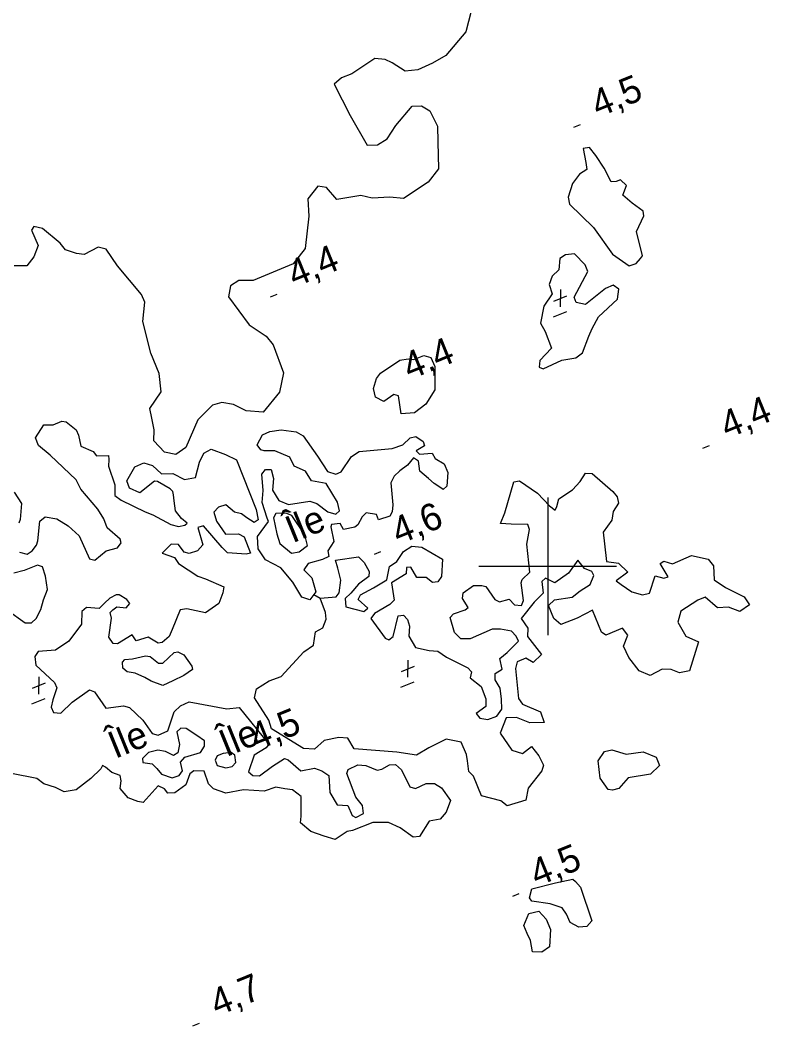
# Model space of a CAD drawing. Extents: x 362852 to 366875, y 5563573 to 5566479.
# Drawn here: x 364723.3 to 364831.6, y 5565333.2 to 5565479.3 of the extents above; entities that cross this region are included whole.
import ezdxf

# ---------------------------------------------------------------- set-up
doc = ezdxf.new("R2010")
doc.units = 0
for name, color, linetype in [('Niveau 3', 7, 'Continuous'), ('Niveau 4', 7, 'Continuous'), ('Niveau 61', 7, 'Continuous'), ('Niveau 8', 7, 'Continuous')]:
    doc.layers.add(name, color=color, linetype=linetype)

msp = doc.modelspace()

# ---------------------------------------------------------------- linework, layer by layer
at = {"layer": 'Niveau 3'}
for p, q in [((364803.8, 5565463.79), (364804.76, 5565464.18)), ((364801.85, 5565440.19), (364801.8, 5565437.67)), ((364759.71, 5565439.11), (364760.67, 5565439.5)), ((364800.91, 5565438.51), (364802.8, 5565439.3)), ((364800.83, 5565436.23), (364802.77, 5565437.02)), ((364822.55, 5565417.14), (364823.51, 5565417.53)), ((364774.81, 5565401.74), (364775.77, 5565402.13)), ((364779.68, 5565386.38), (364779.63, 5565383.87)), ((364778.74, 5565384.7), (364780.63, 5565385.49)), ((364725.13, 5565382.28), (364727.02, 5565383.07)), ((364726.07, 5565383.96), (364726.02, 5565381.44)), ((364778.66, 5565382.42), (364780.6, 5565383.21)), ((364725.05, 5565380), (364726.99, 5565380.79)), ((364794.91, 5565352.07), (364795.87, 5565352.46)), ((364748.44, 5565333.24), (364749.4, 5565333.63))]:
    msp.add_line(p, q, dxfattribs=at)
at = {"layer": 'Niveau 4'}
msp.add_line((364766.02, 5565395.89), (364766.96, 5565395.38), dxfattribs=at)
for points in [[(364789.2, 5565481.95), (364788.11, 5565477.64), (364785.18, 5565474.19), (364783.27, 5565473.09), (364781.14, 5565472.09), (364779.29, 5565471.89), (364777.42, 5565473.11), (364776.4, 5565473.62), (364774.86, 5565473.74), (364771.55, 5565471.5), (364770.04, 5565470.94), (364768.99, 5565470.01), (364771.3, 5565465.48), (364773.77, 5565461.14), (364775.25, 5565461.19), (364776.68, 5565462.09), (364777.93, 5565464.04), (364780.32, 5565466.83), (364781.67, 5565466.89), (364782.85, 5565466.13), (364784.01, 5565463.93), (364784.02, 5565461.63), (364784.15, 5565457.7), (364782.65, 5565455.77), (364779.07, 5565453.42), (364777.08, 5565453.6), (364774.51, 5565453.47), (364772.86, 5565453.85), (364769.37, 5565453.28), (364767.84, 5565455.02), (364766.59, 5565455.19), (364765.17, 5565453.36), (364765.27, 5565450.85), (364764.78, 5565446.16), (364763.02, 5565443.94), (364757.19, 5565441.48), (364755.13, 5565441.5), (364753.89, 5565440.74), (364753.62, 5565439.13), (364756.6, 5565435.07), (364759.09, 5565433.41), (364760.11, 5565432.15), (364761.6, 5565428.09), (364761.01, 5565425.3), (364758.66, 5565422.4), (364756.17, 5565422.55), (364754.35, 5565423.49), (364752.67, 5565423.79), (364751.28, 5565423.4), (364749.17, 5565421.29), (364747.41, 5565417.26), (364745.96, 5565416.23), (364744.34, 5565416.56), (364742.78, 5565418.22), (364742.81, 5565419.79), (364742.47, 5565421.52), (364742.21, 5565422.91), (364743.83, 5565425.32), (364743.53, 5565428), (364742.32, 5565430.93), (364741.16, 5565435.56), (364741.49, 5565438.37), (364740.98, 5565439.47), (364737.51, 5565443.65), (364735.83, 5565446.07), (364734.71, 5565446.36), (364732.67, 5565445.27), (364731.55, 5565445.43), (364729.96, 5565445.96), (364729.18, 5565446.94), (364726.62, 5565449.07), (364725.33, 5565449.34), (364724.98, 5565448.83), (364725.96, 5565446.61), (364725.35, 5565444.93), (364724.32, 5565443.63), (364722.47, 5565443.62)], [(364803.59, 5565455.57), (364802.96, 5565453.62), (364803.14, 5565452.58), (364806.64, 5565449.22), (364809.43, 5565445.33), (364811.81, 5565443.63), (364812.84, 5565443.99), (364813.48, 5565444.69), (364813.75, 5565445.11), (364812.92, 5565448.63), (364813.98, 5565450.88), (364813.88, 5565451.58), (364812.28, 5565452.73), (364810.92, 5565453.92), (364811.46, 5565455.32), (364810.57, 5565456.14), (364809.93, 5565455.87), (364809.2, 5565455.82), (364808.19, 5565457.83), (364807, 5565459.65), (364806.08, 5565460.83), (364805.14, 5565460.69), (364805.56, 5565458.62), (364805.67, 5565457.61), (364804.64, 5565456.93), (364803.59, 5565455.57)], [(364800.2, 5565440.93), (364800.64, 5565439.56), (364799.45, 5565437.76), (364798.97, 5565435.32), (364799.65, 5565434.11), (364800.54, 5565431.67), (364798.86, 5565429.86), (364798.74, 5565428.94), (364799.34, 5565428.68), (364802.06, 5565429.93), (364804.1, 5565430.27), (364805.05, 5565430.98), (364805.97, 5565433.41), (364806.44, 5565434.54), (364807.36, 5565436.23), (364810.15, 5565438.81), (364810.31, 5565440.24), (364809.5, 5565440.84), (364808.41, 5565440.33), (364805.51, 5565438.01), (364804.13, 5565438.32), (364803.83, 5565439.07), (364805.82, 5565442.82), (364805.43, 5565443.78), (364803.89, 5565445.39), (364802.59, 5565445.22), (364801.75, 5565444.69), (364801.61, 5565443.07), (364800.64, 5565442.11), (364800.2, 5565440.93)], [(364778.73, 5565422.12), (364778.32, 5565424.76), (364777.62, 5565424.96), (364776.17, 5565423.93), (364774.98, 5565424.56), (364774.71, 5565425.82), (364775.1, 5565427.29), (364775.72, 5565428.04), (364778.49, 5565429.93), (364779.71, 5565430.13), (364780.56, 5565430.04), (364781.99, 5565430.63), (364783, 5565430.3), (364783.61, 5565428.99), (364783.62, 5565425.63), (364782.31, 5565423.53), (364780.65, 5565422.29), (364778.73, 5565422.12)], [(364723.28, 5565402.04), (364724.39, 5565401.75), (364725.12, 5565402.24), (364725.72, 5565403.05), (364725.9, 5565403.68), (364726.21, 5565406.55), (364727, 5565407.19), (364728.68, 5565406.88), (364730.34, 5565405.89), (364731.94, 5565404.43), (364733.45, 5565401.06), (364734.21, 5565400.88), (364735.83, 5565402.23), (364737.51, 5565402.67), (364738.03, 5565403.39), (364737.86, 5565403.94), (364735.99, 5565405.6), (364735.52, 5565406.9), (364734.64, 5565408.28), (364732.19, 5565411.2), (364731.51, 5565412.54), (364727.72, 5565416.14), (364726.02, 5565417.56), (364725.58, 5565418.63), (364726.77, 5565420.55), (364728.14, 5565420.55), (364729.42, 5565421.08), (364730.03, 5565420.96), (364731.49, 5565419.82), (364731.82, 5565419.02), (364732.17, 5565417.42), (364733.98, 5565416.67), (364734.42, 5565416.04), (364736.2, 5565416.09), (364736.26, 5565415.49), (364736.17, 5565414.52), (364737.09, 5565411.84), (364737.1, 5565410.29), (364738.01, 5565409.61), (364741.52, 5565407.88), (364742.63, 5565407.46), (364745.26, 5565406.06), (364746.37, 5565405.77), (364747.29, 5565405.96), (364747.6, 5565406.27), (364746.77, 5565406.93), (364745.92, 5565408.07), (364745.71, 5565409.48), (364745.65, 5565410.39), (364745.53, 5565410.84), (364745.17, 5565411.25), (364743.31, 5565412.29), (364742.85, 5565412.35), (364740.74, 5565410.67), (364739.22, 5565411.35), (364738.85, 5565412.39), (364740.01, 5565414.42), (364741.31, 5565415.02), (364742.6, 5565414.61), (364743.91, 5565413.41), (364745.51, 5565413.45), (364747.23, 5565412.6), (364748.85, 5565412.89), (364749.42, 5565415.12), (364750.06, 5565416.44), (364751.08, 5565416.99), (364753.19, 5565416.24), (364754.76, 5565415.45), (364757.62, 5565408.22), (364757.92, 5565406.73), (364757.33, 5565406.36), (364756.3, 5565407.05), (364755.51, 5565407.6), (364754.47, 5565407.86), (364753.23, 5565408.9), (364752.18, 5565408.59), (364751.48, 5565407.87), (364751.9, 5565406.55), (364753.18, 5565404.65), (364755.09, 5565404.69)], [(364769.16, 5565400.9), (364772.52, 5565401.35), (364773.34, 5565400.56), (364774.07, 5565399.25), (364774, 5565398.53), (364772.52, 5565397.42), (364771.4, 5565396.09), (364770.59, 5565395.32), (364770.66, 5565394.1), (364773.3, 5565393.44), (364773.85, 5565393.92), (364772.47, 5565395.16), (364772.8, 5565395.85), (364774.68, 5565396.88), (364776.62, 5565398.05), (364777.01, 5565399.96), (364778.07, 5565400.71), (364779.03, 5565402.16), (364780.27, 5565402.92), (364781.7, 5565402.76), (364784.72, 5565401.02), (364784.57, 5565398.53), (364784.02, 5565397.74), (364783.27, 5565397.62), (364782.34, 5565398.36), (364780.97, 5565398.35), (364780.1, 5565399.86), (364779.5, 5565399.8), (364779.44, 5565398.9), (364777.31, 5565397.59), (364777.67, 5565395.06), (364777.06, 5565394.43), (364774.85, 5565393.15), (364774.28, 5565392.42), (364776.4, 5565389.55), (364776.92, 5565389.33), (364777.55, 5565389.78), (364778.28, 5565392.82), (364779.06, 5565392.89), (364779.63, 5565392.26), (364779.9, 5565391.31), (364779.82, 5565389.84), (364780.81, 5565388.19), (364782.79, 5565387.77), (364784.02, 5565387.65), (364785.3, 5565386.81), (364788.37, 5565385.27), (364788.92, 5565384.68), (364788.72, 5565383.8), (364790.31, 5565382.52), (364791.03, 5565380.76), (364791, 5565379.63), (364789.62, 5565378.62), (364790.14, 5565377.96), (364791.28, 5565377.75), (364792.63, 5565378.24), (364793.35, 5565379.22), (364793.3, 5565380.7), (364793.08, 5565382.29), (364792.34, 5565383.48), (364792.38, 5565384.43), (364793.38, 5565385.03), (364793.05, 5565386.58), (364794.12, 5565387.45), (364795.73, 5565389.11), (364795.43, 5565389.86), (364794.76, 5565390.58), (364793.15, 5565390.85), (364791.91, 5565390.84), (364788.74, 5565389.47), (364787.38, 5565389.47), (364786.44, 5565390.39), (364785.85, 5565392.57), (364786.32, 5565393.08), (364788.01, 5565393.65), (364788.43, 5565394.01), (364787.64, 5565395.31), (364787.73, 5565396.15), (364789.22, 5565397.21), (364790.41, 5565397.2), (364791.02, 5565397.07), (364792.3, 5565395.17), (364793, 5565394.84), (364794.39, 5565395.23), (364795.16, 5565394.42), (364796.21, 5565394.29), (364796.47, 5565395.02), (364796.16, 5565397.57), (364796.27, 5565398.06), (364797.38, 5565399.14), (364796.95, 5565403.19), (364797.36, 5565405.36), (364797.13, 5565406.07), (364794.68, 5565406.12), (364793.15, 5565406.23), (364793.77, 5565407.74), (364795.07, 5565412.26), (364795.88, 5565412.41), (364798.49, 5565410.62), (364800.24, 5565408.79), (364801.07, 5565408.13)], [(364801.07, 5565408.13), (364801.34, 5565408.68), (364801.63, 5565409.79), (364803.58, 5565411.1), (364804.7, 5565412.3), (364805.5, 5565413.51), (364806.46, 5565413.47), (364809.47, 5565410.84), (364810.08, 5565410.1), (364810.27, 5565409.18), (364809.49, 5565407.93), (364809.32, 5565406.67), (364808.04, 5565404.96), (364808.25, 5565403.24), (364808.56, 5565400.69), (364810.27, 5565400.46), (364811.62, 5565399.15), (364809.95, 5565397.9), (364810.69, 5565397.33), (364812.24, 5565396.29), (364813.78, 5565395.87), (364814.8, 5565396.1), (364815.63, 5565398.62), (364816.89, 5565398.27), (364817.5, 5565398.46), (364816.32, 5565400.41), (364816.86, 5565400.75), (364818.15, 5565400.35), (364820.89, 5565401.54), (364823.33, 5565401.05), (364824.06, 5565400.04), (364824.2, 5565398.05), (364825.85, 5565396.92), (364828.53, 5565395.54), (364829.3, 5565394.42), (364827.91, 5565393.41), (364826.28, 5565394.05), (364824.65, 5565393.94), (364822.88, 5565395.51), (364821.82, 5565395.07), (364819.36, 5565393.5), (364818.91, 5565391.88), (364820.05, 5565389.86), (364821.9, 5565389), (364820.59, 5565384.79), (364819.15, 5565384.51), (364817.95, 5565385.01), (364816.64, 5565385.03), (364814.9, 5565384.12), (364813.3, 5565384.83), (364811.76, 5565386.75), (364811.02, 5565388.38), (364811.66, 5565390.01), (364810.88, 5565391), (364808.43, 5565389.99), (364807.82, 5565390.42), (364806.5, 5565393.62), (364804.3, 5565392.46), (364801.89, 5565391.53), (364800.9, 5565392.43), (364800.13, 5565394.29), (364800.96, 5565395.13), (364803.54, 5565395.51), (364804.72, 5565396.43), (364806.15, 5565397.33), (364806.71, 5565398.68), (364806.42, 5565399.25), (364805.36, 5565399.69), (364804.37, 5565400.9), (364803.04, 5565398.98), (364801.01, 5565397.58), (364799.67, 5565398.27), (364799.12, 5565397.8), (364799.33, 5565396.08), (364798.05, 5565394.8), (364796.12, 5565392.39), (364797.13, 5565391), (364797.07, 5565389.79), (364799.08, 5565387.19), (364797.88, 5565386.01), (364796.82, 5565386.63), (364795.54, 5565386.11), (364795.32, 5565385.14), (364795.75, 5565380.78), (364796.34, 5565379.96), (364798.97, 5565378.86), (364799.48, 5565377.33), (364797.39, 5565377.28), (364795.45, 5565378.04), (364793.98, 5565377.99), (364793.1, 5565375.76), (364794.8, 5565373.28), (364796.32, 5565372.79), (364797.63, 5565373.83), (364798.69, 5565372.46), (364799.37, 5565371.12), (364799.15, 5565370.28), (364797.14, 5565367.77), (364796.81, 5565366.01), (364794.09, 5565365.21), (364793.17, 5565365.95)], [(364722.48, 5565410.75), (364723.53, 5565409.12), (364723.36, 5565406.81), (364723.14, 5565406.28)], [(364760.16, 5565407.03), (364760.62, 5565404.72), (364761.08, 5565403.3), (364762.79, 5565401.88), (364763.88, 5565402.08), (364765.11, 5565403.03), (364764.73, 5565404.55), (364762.82, 5565407.38), (364761.94, 5565407.7), (364760.52, 5565407.67), (364760.16, 5565407.03)], [(364755.09, 5565404.69), (364755.89, 5565404.27), (364756.8, 5565401.91), (364756.17, 5565401.77), (364753.48, 5565401.97), (364752.68, 5565402.7), (364750, 5565405.89), (364749.18, 5565405.61), (364749.9, 5565403.11), (364749.14, 5565402.24), (364747.93, 5565401.86), (364747.17, 5565402.04), (364746.34, 5565403.14), (364745.31, 5565403.21), (364743.98, 5565401.92), (364745.8, 5565401.29), (364746.35, 5565400.4), (364749.16, 5565398.57), (364750.27, 5565398.15), (364752.92, 5565397), (364752.78, 5565396.13), (364752.23, 5565394.6), (364750.3, 5565393.24), (364747.58, 5565393.81), (364746.59, 5565393.65), (364745.46, 5565390.81), (364745, 5565389.81), (364744, 5565388.91), (364743.41, 5565388.85), (364741.94, 5565389.68), (364740.23, 5565389.16), (364739.62, 5565390.03), (364737.49, 5565388.71), (364736.85, 5565388.76), (364736.22, 5565389.68), (364736.62, 5565392.47), (364736.42, 5565393.26), (364736.81, 5565393.67), (364737.38, 5565394.09), (364738.74, 5565393.96), (364739.3, 5565394.57), (364738.86, 5565395.19), (364737.72, 5565395.85), (364737.28, 5565395.85), (364736.37, 5565395.35), (364735.59, 5565394.66), (364734.84, 5565393.87), (364732.99, 5565394.02), (364732.31, 5565393.43), (364732.25, 5565391.6), (364730.42, 5565389.1), (364728.47, 5565387.8), (364725.98, 5565387.64), (364725.49, 5565386.88), (364725.63, 5565385.63), (364728.34, 5565383.14), (364728.67, 5565382.34), (364728.08, 5565380.6), (364727.85, 5565379.51), (364728.21, 5565378.78), (364729.26, 5565378.65), (364730.9, 5565380.26), (364733.45, 5565382.06), (364734.13, 5565381.78), (364735.79, 5565379.41), (364738.39, 5565379.74), (364739.25, 5565379.47), (364741.18, 5565377.65), (364742.54, 5565375.72), (364743.4, 5565375.45), (364744.81, 5565376.09), (364745.73, 5565378.84), (364746.67, 5565379.73), (364747.93, 5565380.31), (364753.38, 5565379.31), (364755.17, 5565379.49), (364759.48, 5565374.17), (364759.08, 5565373.63), (364757.35, 5565372.54), (364756.54, 5565370.15), (364757.14, 5565369.59), (364758.14, 5565369.57), (364760, 5565370.96), (364761.78, 5565372.06), (364762.28, 5565371.9), (364764.13, 5565370.29), (364766.14, 5565370.69), (364767.17, 5565370.3), (364768.21, 5565369.61), (364768.36, 5565367.12), (364769.4, 5565365.36), (364770.94, 5565365.25), (364771.61, 5565363.78), (364772.1, 5565363.49), (364773.23, 5565364.08), (364773.11, 5565365.27), (364772.11, 5565366.48), (364770.83, 5565369.88), (364771.03, 5565370.46), (364772.42, 5565371.16), (364773.57, 5565371.07)], [(364793.17, 5565365.95), (364790.38, 5565366.67), (364789.22, 5565369.49), (364788.55, 5565370.21), (364788.35, 5565371.74), (364788.21, 5565372.68), (364787.41, 5565374.47), (364785.25, 5565374.89), (364782.71, 5565373.65), (364780.93, 5565372.55), (364778.07, 5565372.99), (364771.89, 5565373.49), (364770.94, 5565375.03), (364769.66, 5565375.13), (364767.54, 5565374.69), (364766.13, 5565373.42), (364764.54, 5565373.51), (364759.87, 5565376.39), (364759.47, 5565377.65), (364757.38, 5565380.9), (364757.71, 5565382.22), (364759.55, 5565383.35), (364761.27, 5565384), (364764.59, 5565387.55), (364765.98, 5565388.56), (364766.25, 5565390.48), (364767.32, 5565391.04), (364767.8, 5565392.3), (364767.71, 5565393.26), (364766.96, 5565395.38), (364769.25, 5565395.57), (364769.7, 5565396.13), (364769.93, 5565397.97), (364769.52, 5565399.73), (364769.16, 5565400.9)], [(364721.53, 5565393.6), (364724.09, 5565391.78), (364725.02, 5565391.79), (364725.7, 5565392.39), (364726.34, 5565393.71), (364726.75, 5565395.13), (364727.32, 5565396.61), (364727.02, 5565398.54), (364726.58, 5565399.91), (364725.85, 5565400.17), (364723.94, 5565399.39), (364722.41, 5565399.01)], [(364744.06, 5565382.67), (364742.37, 5565383.29), (364741.46, 5565383.84), (364740.08, 5565384.46), (364738.88, 5565384.65), (364738.28, 5565385.21), (364738.24, 5565386.07), (364738.57, 5565386.45), (364739.66, 5565386.53), (364741.58, 5565387.01), (364742.24, 5565386.91), (364743.46, 5565385.92), (364744.08, 5565385.92), (364745.74, 5565387.48), (364746.26, 5565387.57), (364747.13, 5565387.12), (364748.31, 5565385.48), (364748.38, 5565385.01), (364747.13, 5565384.12), (364745.52, 5565383.34), (364744.06, 5565382.67)], [(364743.87, 5565369.79), (364745.46, 5565369.26), (364746.44, 5565369.6), (364746.95, 5565370.31), (364746.63, 5565371.55), (364747.27, 5565372.25), (364749.54, 5565372.93), (364750.15, 5565373.87), (364750.15, 5565374.62), (364749.02, 5565375.4), (364747.47, 5565376.44), (364746.7, 5565376.5), (364746.12, 5565375.95), (364746.5, 5565374.11), (364746.26, 5565372.89), (364745.61, 5565372.5), (364744.49, 5565373.1), (364743.35, 5565373.31), (364742.01, 5565372.94), (364741.12, 5565372.08), (364741.18, 5565371.48), (364742.51, 5565371.28), (364743.21, 5565370.64), (364743.87, 5565369.79)], [(364751.98, 5565371.08), (364753.25, 5565370.73), (364754.17, 5565370.92), (364754.67, 5565371.5), (364754.54, 5565372.57), (364754, 5565372.97), (364752.83, 5565372.8), (364751.98, 5565372.45), (364751.68, 5565371.82), (364751.98, 5565371.08)], [(364807.61, 5565369.22), (364807.33, 5565371.72), (364808.25, 5565373.1), (364809.33, 5565373.36), (364811.4, 5565372.71), (364813.87, 5565373.05), (364815.75, 5565372.27), (364816.25, 5565371.04), (364814.95, 5565369.82), (364811.69, 5565369.29), (364810.34, 5565367.73), (364809.39, 5565367.47), (364808.78, 5565367.59), (364807.61, 5565369.22)], [(364773.57, 5565371.07), (364775.23, 5565370.38), (364775.91, 5565370.54), (364777.01, 5565371.18), (364777.87, 5565371.22), (364778.76, 5565370.41), (364779.95, 5565367.97), (364780.81, 5565367.7), (364782.36, 5565368.47), (364783.55, 5565368.46), (364784.56, 5565367.81), (364785.87, 5565365.99), (364785.26, 5565364.3), (364784.39, 5565363.26), (364782.77, 5565362.96), (364781.37, 5565360.77), (364780.43, 5565360.63), (364778.55, 5565362.03), (364776.87, 5565362.78), (364774.58, 5565362.76), (364771.63, 5565361.61), (364770.87, 5565361.49), (364769.11, 5565360.32), (364767.5, 5565360.78), (364765.59, 5565361.49), (364764.08, 5565362.73), (364764.17, 5565363.71), (364764.19, 5565365.46), (364764.17, 5565366.57), (364762.9, 5565367.54), (364761.8, 5565367.65), (364760.5, 5565367.92), (364758.81, 5565367.35), (364755.81, 5565367.55), (364753.22, 5565367.04), (364751.46, 5565367.68), (364750.73, 5565368.38), (364750.09, 5565370.24), (364748.57, 5565370.3), (364748, 5565369.87), (364747.42, 5565368.26), (364745.84, 5565367.11), (364744.81, 5565367.06), (364744.31, 5565367.66), (364743.39, 5565368.09), (364741.2, 5565365.7), (364740.46, 5565365.83), (364739.06, 5565366.37), (364737.89, 5565367.7), (364738.05, 5565368.82), (364737.9, 5565369.63), (364736.67, 5565370.06), (364735.74, 5565370.8), (364735.32, 5565371.06), (364735.08, 5565370.59), (364733.61, 5565369.17), (364731.48, 5565367.55), (364729.73, 5565367.26), (364728.48, 5565367.87), (364726.77, 5565368.41), (364725.77, 5565369.18), (364722.1, 5565369.91)], [(364797.69, 5565353.17), (364801.13, 5565354.03), (364803.65, 5565354.57), (364804.04, 5565354.23), (364804.75, 5565353.41), (364806.41, 5565348.48), (364805.68, 5565347.69), (364804.54, 5565347.59), (364803.27, 5565348.25), (364802.71, 5565349.45), (364802.08, 5565350.37), (364800.35, 5565350.97), (364797.69, 5565351.37), (364797.37, 5565351.86), (364797.69, 5565353.17)], [(364796.54, 5565347.84), (364797.25, 5565349.57), (364798.72, 5565349.92), (364799.77, 5565348.74), (364800.39, 5565347.25), (364800.26, 5565344.7), (364799.14, 5565343.93), (364797.81, 5565344), (364797.51, 5565345.62), (364797.02, 5565346.67), (364796.54, 5565347.84)]]:
    msp.add_lwpolyline(points, dxfattribs=at)
msp.add_lwpolyline([(364757.78, 5565417.63), (364758.55, 5565419.07), (364759.65, 5565419.58), (364761.29, 5565419.83), (364763.46, 5565419.54), (364764.45, 5565418.95), (364766.53, 5565416.01), (364768.02, 5565413.76), (364769.23, 5565413.38), (364769.98, 5565413.69), (364771.48, 5565415.93), (364772.62, 5565416.65), (364777.39, 5565417.12), (364778.93, 5565417.63), (364780.01, 5565418.63), (364780.85, 5565418.85), (364781.9, 5565418.11), (364782.09, 5565417.5), (364780.9, 5565416.76), (364781.36, 5565416.26), (364783.22, 5565416.41), (364783.66, 5565415.65), (364784.97, 5565414.89), (364785.5, 5565413.61), (364785.33, 5565411.61), (364784.83, 5565411.15), (364784.32, 5565411.5), (364783.48, 5565412.03), (364782.68, 5565412.76), (364781.44, 5565413.8), (364781.21, 5565415.27), (364780.52, 5565415.73), (364779.64, 5565414.68), (364778.5, 5565413.84), (364777.7, 5565413.07), (364777.22, 5565412.13), (364777.48, 5565408.93), (364777.4, 5565407.91), (364777.05, 5565407.26), (364775.39, 5565406.76), (364775.13, 5565407.53), (364773.6, 5565407.77), (364773.04, 5565407.17), (364772.39, 5565406.03), (364771.98, 5565405.67), (364770.31, 5565405.35), (364769.83, 5565406.22), (364768.58, 5565406.07), (364768.48, 5565405.72), (364768.92, 5565403.6), (364768.05, 5565402.24), (364768.2, 5565401.43), (364767.26, 5565400.98), (364765.21, 5565400.39), (364764.58, 5565399.5), (364765.75, 5565398.31), (364766.33, 5565396.3), (364766.02, 5565395.89), (364765.45, 5565395.13), (364764.29, 5565395.52), (364762.95, 5565397.71), (364761.24, 5565399.75), (364759, 5565400.94), (364757.91, 5565402.55), (364757.85, 5565404.33), (364759.45, 5565406.49), (364759.26, 5565406.97), (364758.49, 5565409.27), (364758.64, 5565411.01), (364758.48, 5565413.37), (364759.01, 5565414.03), (364759.82, 5565414.05), (364760.16, 5565412.76), (364759.99, 5565411.07), (364760.94, 5565409.53), (364762.34, 5565408.98), (364765.44, 5565409.45), (364766.45, 5565409.12), (364768.07, 5565407.92), (364769.2, 5565407.58), (364769.75, 5565408.05), (364769.48, 5565409.31), (364767.8, 5565412.04), (364765.66, 5565412.41), (364764.83, 5565413.81), (364763.15, 5565414.55), (364762.55, 5565415.86), (364760.37, 5565416.77), (364758.82, 5565416.75), (364758.32, 5565416.92), (364757.78, 5565417.63)], close=True, dxfattribs=at)
at = {"layer": 'Niveau 61'}
for p, q in [((364800, 5565410), (364800, 5565390)), ((364790, 5565400), (364810, 5565400))]:
    msp.add_line(p, q, dxfattribs=at)

# ---------------------------------------------------------------- texts
at = {"layer": 'Niveau 3'}
for s, rotation, p in [('4,5  ', 22.09, (364807.31, 5565465.15)), ('4,4  ', 22.09, (364763.22, 5565440.47)), ('    4,4', 22.0899, (364774.53, 5565424.83)), ('4,4  ', 22.09, (364826.06, 5565418.5)), ('4,6  ', 22.09, (364778.32, 5565403.1)), ('    4,5', 22.0899, (364752.25, 5565370.98)), ('4,5  ', 22.09, (364798.42, 5565353.43)), ('4,7  ', 22.09, (364751.95, 5565334.6))]:
    msp.add_text(s, height=3.93, rotation=rotation, dxfattribs=at).set_placement(p)
at = {"layer": 'Niveau 8'}
for p in [(364762.9, 5565403.32), (364753.27, 5565372.26), (364737.15, 5565372.01)]:
    msp.add_text('Île', height=3.93, rotation=22.09, dxfattribs=at).set_placement(p)

doc.saveas('drawing.dxf')
